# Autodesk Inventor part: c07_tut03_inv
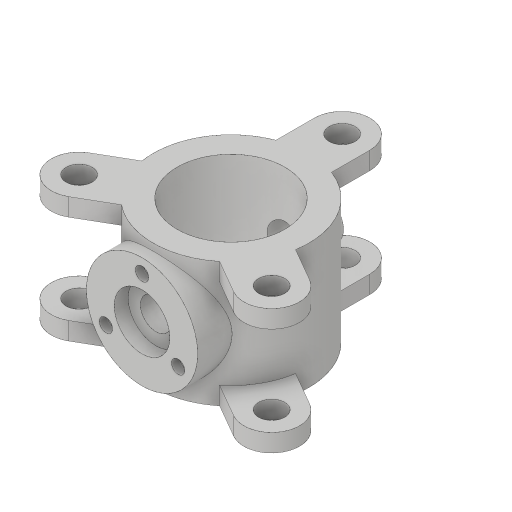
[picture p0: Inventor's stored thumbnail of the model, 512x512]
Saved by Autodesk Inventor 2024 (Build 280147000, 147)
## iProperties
Created: 2017-04
Part Number: c07_tut03_inv
Material: Generic
Document SubType Name: Modeling
Designer: CADCIM 00
Density: 1 g/cm^3
Appearance: Default
Author: CADCIM 00
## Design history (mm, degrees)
sketch "Sketch1"
  geometry: C1 r 140 at (0, 0); C2 r 97 at (0, 0); 1 further point
  constraints: 2 centre point, 2 coincident
  dimensions: "d0" = 280 diameter of C1; "d1" = 194 diameter of C2
extrude "Extrusion1" new body sketch "Sketch1" stored distance "d2" = 225; taper "d3" = 0 deg
workplane "Work Plane1"
sketch "Sketch2"
  geometry: C1 r 100 at (0, 0); 1 further point
  constraints: 1 centre point, 1 coincident
  dimensions: "d5" = 200 diameter of C1
extrude "Extrusion2" join sketch "Sketch2" stored distance "d6" = 225; taper "d7" = 0 deg
workplane "Work Plane2"
sketch "Sketch3"
  geometry: C1 r 37.5 at (0, 0); 1 further point
  constraints: 1 centre point, 1 coincident
  dimensions: "d9" = 75 diameter of C1
extrude "Extrusion3" join sketch "Sketch3" stored distance "d10" = 225; taper "d11" = 0 deg
hole "Hole1" diameter "d14" = 56; stored, may be unused: countersink angle "d18" = 90 deg, drill point angle "d20" = 0 deg; dims "d12" = 10, "d13" = 10, "d15" = 6, "d16" = 100, "d17" = 25, "d19" = 310
sketch "Sketch6"
  geometry: 2 further points
  constraints: 1 vertical alignment
  dimensions: "d21" = 75 distance of point (0, 75) point (0, 0)
hole "Hole2" sketch "Sketch6" diameter "d22" = 24; stored, may be unused: countersink angle "d26" = 90 deg, drill point angle "d28" = 0 deg; dims "d23" = 6, "d24" = 100, "d25" = 25, "d27" = 15
pattern_circular "Circular Pattern1" dims angle "d30" = 360 deg
sketch "Sketch7"
  geometry: L1 (-50, 130.767)-(-50, 200); L2 (50, 200)-(50, 130.767); L3 (0, 0)-(0, 200); C1 r 23.5 at (0, 200); A1 r 50 centre (0, 200) between (50, 200) and (-50, 200); A2 r 140 centre (0, 0) between (-50, 130.767) and (50, 130.767) reference; 1 further point
  constraints: 6 end point, 4 point on circle, 2 centre point, 2 tangent, 2 vertical, 1 coincident, 1 parallel
  dimensions: "d32" = 200 distance of point (0, 0) L3.end; "d34" = 47 diameter of C1; "d40" = 50 radius of A1
extrude "Extrusion4" join sketch "Sketch7" distance "d35" = 32; taper "d36" = 0 deg
pattern_circular "Circular Pattern2" dims angle "d38" = 360 deg
mirror "Mirror1"
body "Solid1"
other parameters: "d8" = 325
